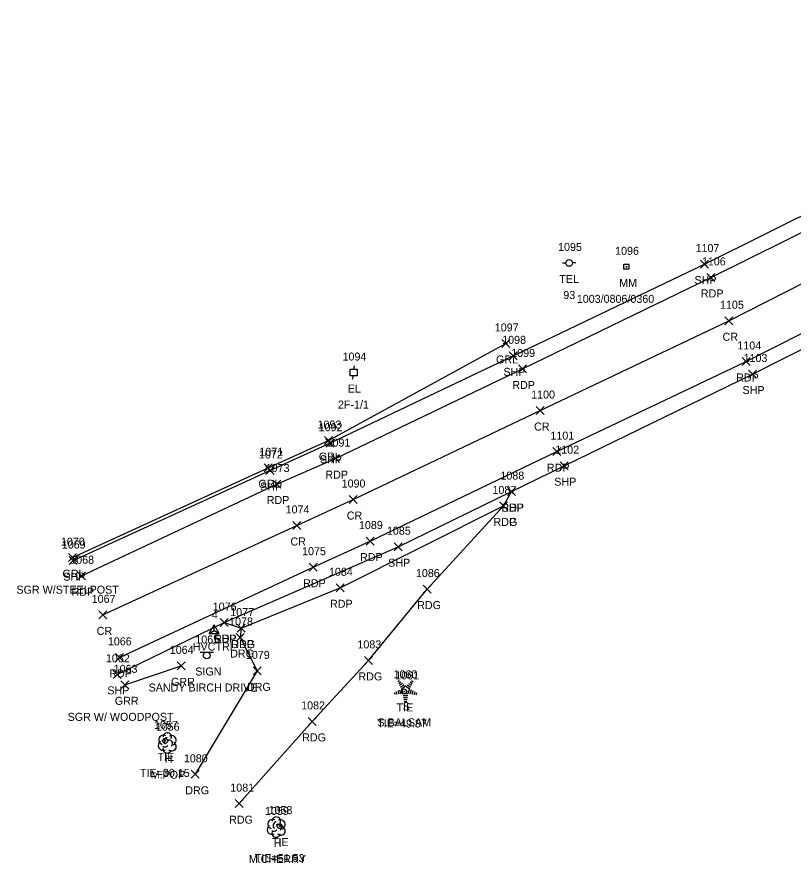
# Model space of a CAD drawing. Extents: x 1606530 to 1613020, y 784959 to 789666.
# Drawn here: x 1608197.4 to 1608391.2, y 787898.7 to 788110.1 of the extents above; entities that cross this region are included whole.
import ezdxf

# ---------------------------------------------------------------- set-up
doc = ezdxf.new("R2010")
doc.units = 0
for name, color, linetype in [('C_A', 7, 'Continuous'), ('C_C', 7, 'Continuous'), ('C_I', 7, 'Continuous'), ('CBP', 7, 'Continuous'), ('CPSM', 7, 'Continuous'), ('L_A', 7, 'Continuous'), ('L_C', 7, 'Continuous'), ('L_I', 7, 'Continuous'), ('LTC', 7, 'Continuous'), ('LTD', 7, 'Continuous'), ('P_A', 7, 'Continuous'), ('P_I', 7, 'Continuous'), ('P_TIC', 7, 'Continuous'), ('PET', 7, 'Continuous'), ('PEU', 7, 'Continuous'), ('PRC', 7, 'Continuous'), ('PSP', 7, 'Continuous'), ('R_A', 7, 'Continuous'), ('R_C', 7, 'Continuous'), ('R_I', 7, 'Continuous'), ('R_TIC', 7, 'Continuous'), ('RDG', 7, 'Continuous'), ('RGR', 7, 'Continuous'), ('S_A', 7, 'Continuous'), ('S_C', 7, 'Continuous'), ('S_I', 7, 'Continuous'), ('SRM', 7, 'Continuous'), ('SSGN', 7, 'Continuous'), ('U_A', 7, 'Continuous'), ('U_C', 7, 'Continuous'), ('U_I', 7, 'Continuous'), ('UEPT', 7, 'Continuous'), ('UP', 7, 'Continuous')]:
    doc.layers.add(name, color=color, linetype=linetype)

msp = doc.modelspace()

# ---------------------------------------------------------------- linework, layer by layer
at = {"layer": 'CBP'}
for centre, radius in [((1608294.08, 787941.57), 0.625), ((1608294.08, 787941.57), 0.0833), ((1608234.37, 787929.23), 0.625), ((1608234.37, 787929.23), 0.0833), ((1608262.97, 787907.93), 0.625), ((1608262.97, 787907.93), 0.0833)]:
    msp.add_circle(centre, radius, dxfattribs=at)
at = {"layer": 'CPSM'}
for p, q in [((1608245.34, 787956.07), (1608246.59, 787958.23)), ((1608245.34, 787956.07), (1608246.59, 787956.79)), ((1608247.84, 787956.07), (1608246.59, 787958.23)), ((1608246.59, 787956.79), (1608246.59, 787958.23)), ((1608246.59, 787956.79), (1608246.59, 787956.79)), ((1608246.59, 787956.79), (1608247.84, 787956.07)), ((1608245.34, 787956.07), (1608247.84, 787956.07))]:
    msp.add_line(p, q, dxfattribs=at)
at = {"layer": 'LTC'}
for p, q in [((1608292.51, 787944.06), (1608292.87, 787944.32)), ((1608292.72, 787943.59), (1608293.25, 787943.98)), ((1608292.93, 787943.13), (1608293.64, 787943.64)), ((1608295.17, 787943.6), (1608295.85, 787943.11)), ((1608295.54, 787943.95), (1608296.09, 787943.55)), ((1608295.91, 787944.3), (1608296.33, 787944)), ((1608292, 787941.56), (1608292.21, 787940.9)), ((1608292.46, 787941.77), (1608292.73, 787940.94)), ((1608292.91, 787941.99), (1608293.24, 787940.97)), ((1608293.14, 787942.66), (1608294.02, 787943.3)), ((1608293.37, 787942.21), (1608294.38, 787942.94)), ((1608293.37, 787942.21), (1608293.75, 787941.01)), ((1608294.38, 787942.94), (1608295.37, 787942.22)), ((1608294.8, 787943.26), (1608295.61, 787942.67)), ((1608295.37, 787942.22), (1608294.98, 787941.01)), ((1608295.81, 787941.95), (1608295.47, 787940.91)), ((1608296.26, 787941.7), (1608295.97, 787940.81)), ((1608296.7, 787941.45), (1608296.46, 787940.72)), ((1608291.55, 787941.34), (1608291.7, 787940.87)), ((1608294.98, 787941.01), (1608293.75, 787941.01)), ((1608294.95, 787940.51), (1608293.8, 787940.51)), ((1608294.86, 787940.01), (1608293.87, 787940.01)), ((1608294.78, 787939.51), (1608293.95, 787939.51)), ((1608297.15, 787941.2), (1608296.96, 787940.62)), ((1608294.69, 787939.01), (1608294.02, 787939.01))]:
    msp.add_line(p, q, dxfattribs=at)
at = {"layer": 'LTD'}
for p, q in [((1608234.86, 787928.77), (1608234.86, 787928.77)), ((1608234.86, 787928.77), (1608234.86, 787928.77)), ((1608262.08, 787907.72), (1608262.08, 787907.72)), ((1608262.08, 787907.72), (1608262.08, 787907.72))]:
    msp.add_line(p, q, dxfattribs=at)
for centre in [(1608234.91, 787930.2), (1608262.13, 787909.16)]:
    msp.add_arc(centre, 1.05, 335.5272, 180.9563, dxfattribs=at)
for centre, major_axis, ratio, start_param, end_param in [((1608234.07, 787929.44), (1.21, -0.51), 0.895232, 1.570796, 4.712389), ((1608233.78, 787928.06), (0.58, -1.04), 0.959034, 3.141593, 6.283185), ((1608234.65, 787929.23), (-0.208, -0.792), 0.645439, 3.141593, 6.283185), ((1608235.36, 787928.6), (-0.5, 0.667), 0.989748, 3.141593, 6.283185), ((1608235.86, 787927.94), (-1.09, 0.79), 0.841452, 1.570796, 4.712389), ((1608235.9, 787929.35), (-1.14, -0.48), 0.949671, 1.570796, 4.712389), ((1608234.86, 787927.27), (0.26, 1.06), 0.942809, 1.570796, 4.712389), ((1608234.4, 787928.02), (-0.625, -0.083), 0.423636, 0, 3.141593), ((1608261.29, 787908.39), (1.21, -0.51), 0.895232, 1.570796, 4.712389), ((1608263.12, 787908.31), (-1.14, -0.48), 0.949671, 1.570796, 4.712389), ((1608261, 787907.01), (0.58, -1.04), 0.959034, 3.141593, 6.283185), ((1608261.87, 787908.18), (-0.208, -0.792), 0.645439, 3.141593, 6.283185), ((1608262.58, 787907.56), (-0.5, 0.667), 0.989748, 3.141593, 6.283185), ((1608263.08, 787906.89), (-1.09, 0.79), 0.841452, 1.570796, 4.712389), ((1608262.08, 787906.22), (0.26, 1.06), 0.942809, 1.570796, 4.712389), ((1608261.62, 787906.97), (-0.625, -0.083), 0.423636, 0, 3.141593)]:
    msp.add_ellipse(centre, major_axis=major_axis, ratio=ratio, start_param=start_param, end_param=end_param, dxfattribs=at)
at = {"layer": 'P_TIC'}
for points in [[(1608368.02, 788047.35), (1608370.02, 788049.35)], [(1608370.02, 788047.35), (1608368.02, 788049.35)], [(1608369.66, 788044.01), (1608371.66, 788046.01)], [(1608371.66, 788044.01), (1608369.66, 788046.01)], [(1608374.14, 788033.19), (1608376.14, 788035.19)], [(1608376.14, 788033.19), (1608374.14, 788035.19)], [(1608320.31, 788024.42), (1608322.31, 788026.42)], [(1608322.31, 788024.42), (1608320.31, 788026.42)], [(1608378.48, 788023.01), (1608380.48, 788025.01)], [(1608380.48, 788023.01), (1608378.48, 788025.01)], [(1608322.57, 788021.14), (1608324.57, 788023.14)], [(1608324.57, 788021.14), (1608322.57, 788023.14)], [(1608380.01, 788019.88), (1608382.01, 788021.88)], [(1608382.01, 788019.88), (1608380.01, 788021.88)], [(1608327.06, 788010.76), (1608329.06, 788012.76)], [(1608329.06, 788010.76), (1608327.06, 788012.76)], [(1608274.47, 788002.59), (1608276.47, 788004.59)], [(1608276.47, 788002.59), (1608274.47, 788004.59)], [(1608275.88, 787998.74), (1608277.88, 788000.74)], [(1608277.88, 787998.74), (1608275.88, 788000.74)], [(1608331.21, 788000.49), (1608333.21, 788002.49)], [(1608333.21, 788000.49), (1608331.21, 788002.49)], [(1608333.01, 787996.98), (1608335.01, 787998.98)], [(1608335.01, 787996.98), (1608333.01, 787998.98)], [(1608259.55, 787995.78), (1608261.55, 787997.78)], [(1608261.55, 787995.78), (1608259.55, 787997.78)], [(1608261.25, 787992.4), (1608263.25, 787994.4)], [(1608263.25, 787992.4), (1608261.25, 787994.4)], [(1608319.86, 787990.5), (1608321.86, 787992.5)], [(1608321.86, 787990.5), (1608319.86, 787992.5)], [(1608319.86, 787990.5), (1608321.86, 787992.5)], [(1608321.86, 787990.5), (1608319.86, 787992.5)], [(1608280.29, 787988.52), (1608282.29, 787990.52)], [(1608282.29, 787988.52), (1608280.29, 787990.52)], [(1608317.88, 787986.93), (1608319.88, 787988.93)], [(1608319.88, 787986.93), (1608317.88, 787988.93)], [(1608317.88, 787986.93), (1608319.88, 787988.93)], [(1608319.88, 787986.93), (1608317.88, 787988.93)], [(1608266.22, 787982.04), (1608268.22, 787984.04)], [(1608268.22, 787982.04), (1608266.22, 787984.04)], [(1608284.55, 787978.14), (1608286.55, 787980.14)], [(1608286.55, 787978.14), (1608284.55, 787980.14)], [(1608291.52, 787976.73), (1608293.52, 787978.73)], [(1608293.52, 787976.73), (1608291.52, 787978.73)], [(1608210.38, 787973.27), (1608212.38, 787975.27)], [(1608212.38, 787973.27), (1608210.38, 787975.27)], [(1608270.33, 787971.62), (1608272.33, 787973.62)], [(1608272.33, 787971.62), (1608270.33, 787973.62)], [(1608212.49, 787969.47), (1608214.49, 787971.47)], [(1608214.49, 787969.47), (1608212.49, 787971.47)], [(1608277.05, 787966.47), (1608279.05, 787968.47)], [(1608279.05, 787966.47), (1608277.05, 787968.47)], [(1608298.81, 787966.15), (1608300.81, 787968.15)], [(1608300.81, 787966.15), (1608298.81, 787968.15)], [(1608217.84, 787959.71), (1608219.84, 787961.71)], [(1608219.84, 787959.71), (1608217.84, 787961.71)], [(1608248.08, 787957.77), (1608250.08, 787959.77)], [(1608250.08, 787957.77), (1608248.08, 787959.77)], [(1608248.08, 787957.77), (1608250.08, 787959.77)], [(1608250.08, 787957.77), (1608248.08, 787959.77)], [(1608252.39, 787956.39), (1608254.39, 787958.39)], [(1608254.39, 787956.39), (1608252.39, 787958.39)], [(1608221.94, 787949.09), (1608223.94, 787951.09)], [(1608223.94, 787949.09), (1608221.94, 787951.09)], [(1608284.15, 787948.33), (1608286.15, 787950.33)], [(1608286.15, 787948.33), (1608284.15, 787950.33)], [(1608221.38, 787944.84), (1608223.38, 787946.84)], [(1608223.38, 787944.84), (1608221.38, 787946.84)], [(1608270.1, 787933.09), (1608272.1, 787935.09)], [(1608272.1, 787933.09), (1608270.1, 787935.09)], [(1608251.85, 787912.54), (1608253.85, 787914.54)], [(1608253.85, 787912.54), (1608251.85, 787914.54)]]:
    msp.add_lwpolyline(points, dxfattribs=at)
at = {"layer": 'PET'}
for points in [[(1608213.49, 787970.47), (1608262.25, 787993.4), (1608276.88, 787999.74), (1608323.57, 788022.14), (1608370.66, 788045.01), (1608417.98, 788068.46), (1608464.64, 788091.66), (1608509.37, 788115.25), (1608554.28, 788138.75), (1608602.43, 788165), (1608652.45, 788192.19), (1608697.7, 788217.31), (1608740.32, 788241.6), (1608780.44, 788265.54), (1608814.8, 788285.27), (1608858.1, 788310.73), (1608896.56, 788332.46)], [(1608222.94, 787950.09), (1608271.33, 787972.62), (1608285.55, 787979.14), (1608332.21, 788001.49), (1608379.48, 788024.01), (1608428.02, 788048.6), (1608475.06, 788071.87), (1608519, 788095), (1608563.86, 788118.44), (1608613.21, 788145.21), (1608663.01, 788172.64), (1608706.97, 788197.28), (1608750.94, 788222.17), (1608791.64, 788245.74), (1608827.2, 788266.24), (1608867.86, 788290.54)], [(1608249.08, 787958.77), (1608253.39, 787957.39), (1608278.05, 787967.47), (1608318.88, 787987.93), (1608320.86, 787991.5)]]:
    msp.add_lwpolyline(points, dxfattribs=at)
at = {"layer": 'PEU'}
msp.add_lwpolyline([(1608252.85, 787913.54), (1608271.1, 787934.09), (1608285.15, 787949.33), (1608299.81, 787967.15), (1608318.88, 787987.93)], dxfattribs=at)
at = {"layer": 'PRC'}
msp.add_lwpolyline([(1608218.84, 787960.71), (1608267.22, 787983.04), (1608281.29, 787989.52), (1608328.06, 788011.76), (1608375.14, 788034.19), (1608423.06, 788058.55), (1608469.95, 788081.45), (1608514.06, 788104.91), (1608558.92, 788128.79), (1608607.88, 788155.22), (1608657.8, 788182.27), (1608701.47, 788207.47), (1608744.76, 788231.88), (1608785.13, 788255.45), (1608820.6, 788275.76), (1608863.25, 788300.9), (1608901.81, 788322.6)], dxfattribs=at)
at = {"layer": 'PSP'}
for points in [[(1608211.38, 787974.27), (1608260.55, 787996.78), (1608275.47, 788003.59), (1608321.31, 788025.42), (1608369.02, 788048.35), (1608416.07, 788071.69), (1608462.93, 788095.28), (1608507.55, 788118.54), (1608552.21, 788141.92), (1608600.4, 788168.18), (1608650.82, 788195.72), (1608695.96, 788221.19), (1608744.94, 788249.39), (1608760.2, 788258.36), (1608792.98, 788277.31), (1608812.41, 788289.29), (1608855.39, 788314.11), (1608894.81, 788336.59)], [(1608222.38, 787945.84), (1608249.08, 787958.77), (1608292.52, 787977.73), (1608320.86, 787991.5), (1608334.01, 787997.98), (1608381.01, 788020.88), (1608430, 788045.59), (1608476.4, 788068.65), (1608521.08, 788091.65), (1608567.38, 788116.6), (1608615.07, 788142.28), (1608664.87, 788169.33), (1608708.99, 788194), (1608752.22, 788219.24), (1608792.93, 788243.28), (1608830.36, 788265), (1608869.22, 788287.4)]]:
    msp.add_lwpolyline(points, dxfattribs=at)
at = {"layer": 'R_TIC'}
for points in [[(1608318.46, 788027.52), (1608320.46, 788029.52)], [(1608320.46, 788027.52), (1608318.46, 788029.52)], [(1608274.2, 788003.25), (1608276.2, 788005.25)], [(1608276.2, 788003.25), (1608274.2, 788005.25)], [(1608259.1, 787996.45), (1608261.1, 787998.45)], [(1608261.1, 787996.45), (1608259.1, 787998.45)], [(1608210.19, 787974), (1608212.19, 787976)], [(1608212.19, 787974), (1608210.19, 787976)], [(1608252.39, 787956.39), (1608254.39, 787958.39)], [(1608254.39, 787956.39), (1608252.39, 787958.39)], [(1608252.11, 787954.05), (1608254.11, 787956.05)], [(1608254.11, 787954.05), (1608252.11, 787956.05)], [(1608237.34, 787946.97), (1608239.34, 787948.97)], [(1608239.34, 787946.97), (1608237.34, 787948.97)], [(1608256.31, 787945.72), (1608258.31, 787947.72)], [(1608258.31, 787945.72), (1608256.31, 787947.72)], [(1608223.32, 787942.23), (1608225.32, 787944.23)], [(1608225.32, 787942.23), (1608223.32, 787944.23)], [(1608240.9, 787919.87), (1608242.9, 787921.87)], [(1608242.9, 787919.87), (1608240.9, 787921.87)]]:
    msp.add_lwpolyline(points, dxfattribs=at)
at = {"layer": 'RDG'}
msp.add_lwpolyline([(1608253.39, 787957.39), (1608253.11, 787955.05), (1608257.31, 787946.72), (1608241.9, 787920.87)], dxfattribs=at)
at = {"layer": 'RGR'}
for points in [[(1608211.19, 787975), (1608260.1, 787997.45), (1608275.2, 788004.25), (1608319.46, 788028.52)], [(1608224.32, 787943.23), (1608238.34, 787947.97)]]:
    msp.add_lwpolyline(points, dxfattribs=at)
at = {"layer": 'SRM'}
msp.add_lwpolyline([(1608348.95, 788048.29), (1608350.2, 788048.29), (1608350.2, 788047.04), (1608348.95, 788047.04)], close=True, dxfattribs=at)
msp.add_circle((1608349.57, 788047.66), 0.0833, dxfattribs=at)
at = {"layer": 'SSGN'}
for p, q in [((1608243.1, 787951.42), (1608246.44, 787951.42)), ((1608244.75, 787950.58), (1608244.75, 787950.58))]:
    msp.add_line(p, q, dxfattribs=at)
msp.add_circle((1608244.75, 787950.58), 0.833, dxfattribs=at)
at = {"layer": 'UEPT'}
for p, q in [((1608280.61, 788020.42), (1608280.61, 788022.09)), ((1608280.61, 788022.09), (1608282.28, 788022.09)), ((1608281.61, 788022.92), (1608281.44, 788022.09)), ((1608282.28, 788022.09), (1608282.28, 788020.42)), ((1608282.28, 788020.42), (1608280.61, 788020.42)), ((1608281.19, 788019.59), (1608281.44, 788020.42)), ((1608281.44, 788021.25), (1608281.44, 788021.25))]:
    msp.add_line(p, q, dxfattribs=at)
at = {"layer": 'UP'}
for p, q in [((1608333.6, 788048.62), (1608334.43, 788048.62)), ((1608335.26, 788048.62), (1608335.26, 788048.62)), ((1608336.93, 788048.62), (1608336.1, 788048.62)), ((1608336.1, 788048.62), (1608336.1, 788048.62)), ((1608336.93, 788048.62), (1608336.93, 788048.62))]:
    msp.add_line(p, q, dxfattribs=at)
msp.add_circle((1608335.26, 788048.62), 0.833, dxfattribs=at)

# ---------------------------------------------------------------- texts
at = {"layer": 'C_A'}
for s, p in [('HVCTRL', (1608241.28, 787951.79)), ('TIE', (1608292.16, 787936.57)), ('TIE', (1608232.44, 787924.23)), ('TIE', (1608261.04, 787902.93))]:
    msp.add_text(s, height=2, dxfattribs=at).set_placement(p)
at = {"layer": 'C_C'}
for s, p in [('TIE=49.87', (1608287.31, 787932.57)), ('TIE=30.15', (1608228.08, 787920.23)), ('TIE=51.53', (1608256.76, 787898.93))]:
    msp.add_text(s, height=2, dxfattribs=at).set_placement(p)
at = {"layer": 'C_I'}
for s, p in [('4', (1608246.02, 787959.79)), ('1061', (1608291.83, 787944.57)), ('1057', (1608231.59, 787932.23)), ('1058', (1608260.19, 787910.93))]:
    msp.add_text(s, height=2, dxfattribs=at).set_placement(p)
at = {"layer": 'L_A'}
for s, p in [('S', (1608293.7, 787936.85)), ('H', (1608234.29, 787923.77)), ('H', (1608261.51, 787902.72))]:
    msp.add_text(s, height=2, dxfattribs=at).set_placement(p)
at = {"layer": 'L_C'}
for s, p in [('S.BALSAM', (1608287.4, 787932.85)), ('M.POP', (1608230.76, 787919.77)), ('M.CHERRY', (1608255.26, 787898.72))]:
    msp.add_text(s, height=2, dxfattribs=at).set_placement(p)
at = {"layer": 'L_I'}
for s, p in [('1060', (1608291.41, 787944.85)), ('1056', (1608232.03, 787931.77)), ('1059', (1608259.3, 787910.72))]:
    msp.add_text(s, height=2, dxfattribs=at).set_placement(p)
at = {"layer": 'LTC'}
msp.add_text('.', height=1.04, rotation=270, dxfattribs=at).set_placement((1608294.26, 787941.96))
at = {"layer": 'P_A'}
for s, p in [('SHP', (1608366.56, 788043.35)), ('RDP', (1608368.15, 788040.01)), ('CR', (1608373.57, 788029.19)), ('SHP', (1608318.85, 788020.42)), ('RDP', (1608376.97, 788019.01)), ('RDP', (1608321.06, 788017.14)), ('SHP', (1608378.55, 788015.88)), ('CR', (1608326.49, 788006.76)), ('SHP', (1608273.01, 787998.59)), ('RDP', (1608329.7, 787996.49)), ('RDP', (1608274.37, 787994.74)), ('SHP', (1608331.54, 787992.98)), ('SHP', (1608258.09, 787991.78)), ('RDP', (1608259.74, 787988.4)), ('SHP', (1608318.4, 787986.5)), ('RDP', (1608318.35, 787986.5)), ('CR', (1608279.73, 787984.52)), ('RDG', (1608316.37, 787982.93)), ('RDP', (1608316.37, 787982.93)), ('CR', (1608265.66, 787978.04)), ('RDP', (1608283.04, 787974.14)), ('SHP', (1608290.06, 787972.73)), ('SHP', (1608208.91, 787969.27)), ('RDP', (1608268.82, 787967.62)), ('RDP', (1608210.98, 787965.47)), ('RDP', (1608275.54, 787962.47)), ('RDG', (1608297.3, 787962.15)), ('CR', (1608217.27, 787955.71)), ('SHP', (1608246.62, 787953.77)), ('RDP', (1608246.57, 787953.77)), ('RDP', (1608250.88, 787952.39)), ('RDP', (1608220.42, 787945.09)), ('RDG', (1608282.64, 787944.33)), ('SHP', (1608219.92, 787940.84)), ('RDG', (1608268.59, 787929.09)), ('RDG', (1608250.34, 787908.54))]:
    msp.add_text(s, height=2, dxfattribs=at).set_placement(p)
at = {"layer": 'P_I'}
for s, p in [('1107', (1608366.82, 788051.35)), ('1106', (1608368.4, 788048.01)), ('1105', (1608372.93, 788037.19)), ('1098', (1608318.54, 788028.42)), ('1104', (1608377.27, 788027.01)), ('1099', (1608320.79, 788025.14)), ('1103', (1608378.81, 788023.88)), ('1100', (1608325.77, 788014.76)), ('1092', (1608272.7, 788006.59)), ('1101', (1608330.58, 788004.49)), ('1091', (1608274.67, 788002.74)), ('1102', (1608331.8, 788000.98)), ('1072', (1608257.78, 787999.78)), ('1073', (1608259.48, 787996.4)), ('1088', (1608318.09, 787994.5)), ('1088', (1608318.09, 787994.5)), ('1090', (1608278.44, 787992.52)), ('1087', (1608316.11, 787990.93)), ('1087', (1608316.11, 787990.93)), ('1074', (1608264.45, 787986.04)), ('1089', (1608282.77, 787982.14)), ('1085', (1608289.75, 787980.73)), ('1069', (1608208.55, 787977.27)), ('1075', (1608268.56, 787975.62)), ('1068', (1608210.67, 787973.47)), ('1084', (1608275.28, 787970.47)), ('1086', (1608296.99, 787970.15)), ('1067', (1608216.02, 787963.71)), ('1076', (1608246.25, 787961.77)), ('1076', (1608246.25, 787961.77)), ('1077', (1608250.62, 787960.39)), ('1066', (1608220.06, 787953.09)), ('1083', (1608282.38, 787952.33)), ('1062', (1608219.56, 787948.84)), ('1082', (1608268.33, 787937.09)), ('1081', (1608250.64, 787916.54))]:
    msp.add_text(s, height=2, dxfattribs=at).set_placement(p)
at = {"layer": 'R_A'}
for s, p in [('GRL', (1608317.01, 788023.52)), ('GRL', (1608272.74, 787999.25)), ('GRL', (1608257.64, 787992.45)), ('GRL', (1608208.73, 787970)), ('DRG', (1608250.88, 787952.39)), ('DRG', (1608250.6, 787950.05)), ('GRR', (1608235.83, 787942.97)), ('DRG', (1608254.8, 787941.72)), ('GRR', (1608221.8, 787938.23)), ('DRG', (1608239.39, 787915.87))]:
    msp.add_text(s, height=2, dxfattribs=at).set_placement(p)
at = {"layer": 'R_C'}
for s, p in [('SGR W/STEELPOST', (1608197.23, 787966)), ('SGR W/ WOODPOST', (1608210.02, 787934.23))]:
    msp.add_text(s, height=2, dxfattribs=at).set_placement(p)
at = {"layer": 'R_I'}
for s, p in [('1097', (1608316.69, 788031.52)), ('1093', (1608272.43, 788007.25)), ('1071', (1608257.89, 788000.45)), ('1070', (1608208.33, 787978)), ('1077', (1608250.62, 787960.39)), ('1078', (1608250.34, 787958.05)), ('1064', (1608235.52, 787950.97)), ('1079', (1608254.53, 787949.72)), ('1063', (1608221.5, 787946.23)), ('1080', (1608239.04, 787923.87))]:
    msp.add_text(s, height=2, dxfattribs=at).set_placement(p)
at = {"layer": 'S_A'}
for s, p in [('MM', (1608347.76, 788042.66)), ('SIGN', (1608241.89, 787945.56))]:
    msp.add_text(s, height=2, dxfattribs=at).set_placement(p)
at = {"layer": 'S_C'}
for s, p in [('1003/0806/0360', (1608337.17, 788038.66)), ('SANDY BIRCH DRIVE', (1608230.23, 787941.56))]:
    msp.add_text(s, height=2, dxfattribs=at).set_placement(p)
at = {"layer": 'S_I'}
for s, p in [('1096', (1608346.74, 788050.66)), ('1065', (1608241.91, 787953.56))]:
    msp.add_text(s, height=2, dxfattribs=at).set_placement(p)
at = {"layer": 'U_A'}
for s, p in [('TEL', (1608332.82, 788043.62)), ('EL', (1608279.98, 788016.25))]:
    msp.add_text(s, height=2, dxfattribs=at).set_placement(p)
at = {"layer": 'U_C'}
for s, p in [('93', (1608333.8, 788039.62)), ('2F-1/1', (1608277.52, 788012.25))]:
    msp.add_text(s, height=2, dxfattribs=at).set_placement(p)
at = {"layer": 'U_I'}
for s, p in [('1095', (1608332.49, 788051.62)), ('1094', (1608278.67, 788024.25))]:
    msp.add_text(s, height=2, dxfattribs=at).set_placement(p)

doc.saveas('drawing.dxf')
